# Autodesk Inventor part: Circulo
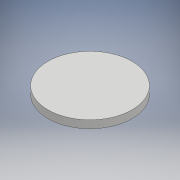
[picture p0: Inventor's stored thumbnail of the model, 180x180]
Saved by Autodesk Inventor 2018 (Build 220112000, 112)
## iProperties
Created: 2020-11
Part Number: Circulo
Material: Genérico
Document SubType Name: Modeling
Designer: ULISES
Density: 1 g/cm^3
Appearance: Valor por defecto
Author: ULISES
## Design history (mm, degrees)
sketch "Boceto1"
  geometry: L1 (0, 0)-(35, 0); L2 (35, 0)-(35, 35); L3 (35, 35)-(0, 35); L4 (0, 35)-(0, 0); C1 r 17.5 at (17.5, 17.5)
  constraints: 8 end point, 3 tangent, 2 parallel, 1 centre point, 1 horizontal, 1 perpendicular
  dimensions: "d0" = 35 distance of L3.end L1.start; "d1" = 35 distance of L2.end L3.end
extrude "Extrusión1" new body sketch "Boceto1" distance "d2" = 3.2; taper "d3" = 0 deg
node "Sólido1"
